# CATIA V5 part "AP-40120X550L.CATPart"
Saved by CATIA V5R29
Part number: AP-40120X550L
Bounding box of the stored display mesh (mm): x -275 to 275, y -60 to 60, z -20 to 20
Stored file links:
  C:\Users\Administrator\Desktop\프로젝트\Boxfold\AP-40120X550L.CATPart
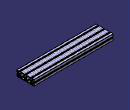
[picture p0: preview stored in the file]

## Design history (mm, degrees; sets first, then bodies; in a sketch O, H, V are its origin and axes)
Body1 (main body)
  Sketch1 on yz-plane, origin (0, 0, 0), H (0, 1, 0), V (0, 0, 1)
    point P1 (-60, -19)
    circle A1 centre (53.5, -13.5) radius 4
    circle A2 centre (53.5, 13.5) radius 4
    circle A3 centre (-53.5, -13.5) radius 4
    circle A4 centre (-53.5, 13.5) radius 4
    arc A5 centre (-38.0088, -3.1185) radius 0.3 from (-37.7966, -2.9064) to (-38.1702, -2.8656) ccw
    line L1 (-37.7966, -2.9064) -> (-37.1018, -3.6012)
    arc A6 centre (-36.8897, -3.3891) radius 0.3 from (-37.1018, -3.6012) to (-36.6868, -3.6101) ccw
    arc A7 centre (-40, 0) radius 4.9 from (-36.6868, -3.6101) to (-36.3857, -3.3086) ccw
    arc A8 centre (-36.607, -3.106) radius 0.3 from (-36.3857, -3.3086) to (-36.3949, -2.8939) ccw
    line L2 (-36.3949, -2.8939) -> (-37.0904, -2.1983)
    arc A9 centre (-36.8783, -1.9862) radius 0.3 from (-37.1314, -1.8252) to (-37.0904, -2.1983) ccw
    arc A10 centre (-40, 0) radius 3.4 from (-37.1314, -1.8252) to (-37.1323, 1.8265) ccw
    arc A11 centre (-36.8792, 1.9877) radius 0.3 from (-37.0914, 2.1998) to (-37.1323, 1.8265) ccw
    line L3 (-37.0914, 2.1998) -> (-36.396, 2.8952)
    arc A12 centre (-36.6081, 3.1073) radius 0.3 from (-36.396, 2.8952) to (-36.3869, 3.31) ccw
    arc A13 centre (-40, 0) radius 4.9 from (-36.3869, 3.31) to (-36.6881, 3.6113) ccw
    arc A14 centre (-36.8909, 3.3902) radius 0.3 from (-36.6881, 3.6113) to (-37.103, 3.6024) ccw
    line L4 (-37.103, 3.6024) -> (-37.7981, 2.9073)
    arc A15 centre (-38.0102, 3.1194) radius 0.3 from (-38.1716, 2.8665) to (-37.7981, 2.9073) ccw
    arc A16 centre (-40, 0) radius 3.4 from (-38.1716, 2.8665) to (-41.8252, 2.8686) ccw
    arc A17 centre (-41.9862, 3.1217) radius 0.3 from (-42.1983, 2.9096) to (-41.8252, 2.8686) ccw
    line L5 (-42.1983, 2.9096) -> (-42.8939, 3.6051)
    arc A18 centre (-43.106, 3.393) radius 0.3 from (-42.8939, 3.6051) to (-43.3086, 3.6143) ccw
    arc A19 centre (-40, 0) radius 4.9 from (-43.3086, 3.6143) to (-43.6101, 3.3132) ccw
    arc A20 centre (-43.3891, 3.1103) radius 0.3 from (-43.6101, 3.3132) to (-43.6012, 2.8982) ccw
    line L6 (-43.6012, 2.8982) -> (-42.9064, 2.2034)
    arc A21 centre (-43.1185, 1.9912) radius 0.3 from (-42.8656, 1.8298) to (-42.9064, 2.2034) ccw
    arc A22 centre (-40, 0) radius 3.4 from (-42.8656, 1.8298) to (-42.8665, -1.8284) ccw
    arc A23 centre (-43.1194, -1.9898) radius 0.3 from (-42.9073, -2.2019) to (-42.8665, -1.8284) ccw
    line L7 (-42.9073, -2.2019) -> (-43.6024, -2.897)
    arc A24 centre (-43.3902, -3.1091) radius 0.3 from (-43.6024, -2.897) to (-43.6113, -3.3119) ccw
    arc A25 centre (-40, 0) radius 4.9 from (-43.6113, -3.3119) to (-43.31, -3.6131) ccw
    arc A26 centre (-43.1073, -3.3919) radius 0.3 from (-43.31, -3.6131) to (-42.8952, -3.604) ccw
    line L8 (-42.8952, -3.604) -> (-42.1998, -2.9086)
    arc A27 centre (-41.9877, -3.1208) radius 0.3 from (-41.8265, -2.8677) to (-42.1998, -2.9086) ccw
    arc A28 centre (-40, 0) radius 3.4 from (-41.8265, -2.8677) to (-38.1702, -2.8656) ccw
    line L9 (39.6951, 6.0049) -> (40, 5.7)
    line L10 (40, 5.7) -> (40.3049, 6.0049)
    arc A29 centre (40, 15.5) radius 9.5 from (40.3049, 6.0049) to (47.0734, 9.1583) ccw
    arc A30 centre (46.85, 9.3585) radius 0.3 from (47.0734, 9.1583) to (47.15, 9.3585) ccw
    line L11 (47.15, 9.3585) -> (47.15, 15.7)
    arc A31 centre (46.85, 15.7) radius 0.3 from (47.15, 15.7) to (46.85, 16) ccw
    line L12 (46.85, 16) -> (44.65, 16)
    arc A32 centre (44.65, 16.5) radius 0.5 from (44.15, 16.5) to (44.65, 16) ccw
    line L13 (44.15, 16.5) -> (44.15, 19.5)
    arc A33 centre (44.65, 19.5) radius 0.5 from (44.65, 20) to (44.15, 19.5) ccw
    line L14 (44.65, 20) -> (59, 20)
    arc A34 centre (59, 19) radius 1 from (60, 19) to (59, 20) ccw
    line L15 (60, 19) -> (60, 4.65)
    arc A35 centre (59.5, 4.65) radius 0.5 from (59.5, 4.15) to (60, 4.65) ccw
    line L16 (59.5, 4.15) -> (56.5, 4.15)
    arc A36 centre (56.5, 4.65) radius 0.5 from (56, 4.65) to (56.5, 4.15) ccw
    line L17 (56, 4.65) -> (56, 6.85)
    arc A37 centre (55.7, 6.85) radius 0.3 from (56, 6.85) to (55.7, 7.15) ccw
    line L18 (55.7, 7.15) -> (49.3585, 7.15)
    arc A38 centre (49.3585, 6.85) radius 0.3 from (49.3585, 7.15) to (49.1583, 7.0734) ccw
    arc A39 centre (55.5, 0) radius 9.5 from (49.1583, 7.0734) to (46.0049, 0.3049) ccw
    line L19 (46.0049, 0.3049) -> (45.7, 0)
    line L20 (45.7, 0) -> (46.0049, -0.3049)
    arc A40 centre (55.5, 0) radius 9.5 from (46.0049, -0.3049) to (49.1583, -7.0734) ccw
    arc A41 centre (49.3585, -6.85) radius 0.3 from (49.1583, -7.0734) to (49.3585, -7.15) ccw
    line L21 (49.3585, -7.15) -> (55.7, -7.15)
    arc A42 centre (55.7, -6.85) radius 0.3 from (55.7, -7.15) to (56, -6.85) ccw
    line L22 (56, -6.85) -> (56, -4.65)
    arc A43 centre (56.5, -4.65) radius 0.5 from (56.5, -4.15) to (56, -4.65) ccw
    line L23 (56.5, -4.15) -> (59.5, -4.15)
    arc A44 centre (59.5, -4.65) radius 0.5 from (60, -4.65) to (59.5, -4.15) ccw
    line L24 (60, -4.65) -> (60, -19)
    arc A45 centre (59, -19) radius 1 from (59, -20) to (60, -19) ccw
    line L25 (59, -20) -> (44.65, -20)
    arc A46 centre (44.65, -19.5) radius 0.5 from (44.15, -19.5) to (44.65, -20) ccw
    line L26 (44.15, -19.5) -> (44.15, -16.5)
    arc A47 centre (44.65, -16.5) radius 0.5 from (44.65, -16) to (44.15, -16.5) ccw
    line L27 (44.65, -16) -> (46.85, -16)
    arc A48 centre (46.85, -15.7) radius 0.3 from (46.85, -16) to (47.15, -15.7) ccw
    line L28 (47.15, -15.7) -> (47.15, -9.3585)
    arc A49 centre (46.85, -9.3585) radius 0.3 from (47.15, -9.3585) to (47.0734, -9.1583) ccw
    arc A50 centre (40, -15.5) radius 9.5 from (47.0734, -9.1583) to (40.3049, -6.0049) ccw
    line L29 (40.3049, -6.0049) -> (40, -5.7)
    line L30 (40, -5.7) -> (39.6951, -6.0049)
    arc A51 centre (40, -15.5) radius 9.5 from (39.6951, -6.0049) to (32.9266, -9.1583) ccw
    arc A52 centre (33.15, -9.3585) radius 0.3 from (32.9266, -9.1583) to (32.85, -9.3585) ccw
    line L31 (32.85, -9.3585) -> (32.85, -15.7)
    arc A53 centre (33.15, -15.7) radius 0.3 from (32.85, -15.7) to (33.15, -16) ccw
    line L32 (33.15, -16) -> (35.35, -16)
    arc A54 centre (35.35, -16.5) radius 0.5 from (35.85, -16.5) to (35.35, -16) ccw
    line L33 (35.85, -16.5) -> (35.85, -19.5)
    arc A55 centre (35.35, -19.5) radius 0.5 from (35.35, -20) to (35.85, -19.5) ccw
    line L34 (35.35, -20) -> (4.65, -20)
    arc A56 centre (4.65, -19.5) radius 0.5 from (4.15, -19.5) to (4.65, -20) ccw
    line L35 (4.15, -19.5) -> (4.15, -16.5)
    arc A57 centre (4.65, -16.5) radius 0.5 from (4.65, -16) to (4.15, -16.5) ccw
    line L36 (4.65, -16) -> (6.85, -16)
    arc A58 centre (6.85, -15.7) radius 0.3 from (6.85, -16) to (7.15, -15.7) ccw
    line L37 (7.15, -15.7) -> (7.15, -9.3585)
    arc A59 centre (6.85, -9.3585) radius 0.3 from (7.15, -9.3585) to (7.0734, -9.1583) ccw
    arc A60 centre (0, -15.5) radius 9.5 from (7.0734, -9.1583) to (0.3049, -6.0049) ccw
    line L38 (0.3049, -6.0049) -> (0, -5.7)
    line L39 (0, -5.7) -> (-0.3049, -6.0049)
    arc A61 centre (0, -15.5) radius 9.5 from (-0.3049, -6.0049) to (-7.0734, -9.1583) ccw
    arc A62 centre (-6.85, -9.3585) radius 0.3 from (-7.0734, -9.1583) to (-7.15, -9.3585) ccw
    line L40 (-7.15, -9.3585) -> (-7.15, -15.7)
    arc A63 centre (-6.85, -15.7) radius 0.3 from (-7.15, -15.7) to (-6.85, -16) ccw
    line L41 (-6.85, -16) -> (-4.65, -16)
    arc A64 centre (-4.65, -16.5) radius 0.5 from (-4.15, -16.5) to (-4.65, -16) ccw
    line L42 (-4.15, -16.5) -> (-4.15, -19.5)
    arc A65 centre (-4.65, -19.5) radius 0.5 from (-4.65, -20) to (-4.15, -19.5) ccw
    line L43 (-4.65, -20) -> (-35.35, -20)
    arc A66 centre (-35.35, -19.5) radius 0.5 from (-35.85, -19.5) to (-35.35, -20) ccw
    line L44 (-35.85, -19.5) -> (-35.85, -16.5)
    arc A67 centre (-35.35, -16.5) radius 0.5 from (-35.35, -16) to (-35.85, -16.5) ccw
    line L45 (-35.35, -16) -> (-33.15, -16)
    arc A68 centre (-33.15, -15.7) radius 0.3 from (-33.15, -16) to (-32.85, -15.7) ccw
    line L46 (-32.85, -15.7) -> (-32.85, -9.3585)
    arc A69 centre (-33.15, -9.3585) radius 0.3 from (-32.85, -9.3585) to (-32.9266, -9.1583) ccw
    arc A70 centre (-40, -15.5) radius 9.5 from (-32.9266, -9.1583) to (-39.6951, -6.0049) ccw
    line L47 (-39.6951, -6.0049) -> (-40, -5.7)
    line L48 (-40, -5.7) -> (-40.3049, -6.0049)
    arc A71 centre (-40, -15.5) radius 9.5 from (-40.3049, -6.0049) to (-47.0734, -9.1583) ccw
    arc A72 centre (-46.85, -9.3585) radius 0.3 from (-47.0734, -9.1583) to (-47.15, -9.3585) ccw
    line L49 (-47.15, -9.3585) -> (-47.15, -15.7)
    arc A73 centre (-46.85, -15.7) radius 0.3 from (-47.15, -15.7) to (-46.85, -16) ccw
    line L50 (-46.85, -16) -> (-44.65, -16)
    arc A74 centre (-44.65, -16.5) radius 0.5 from (-44.15, -16.5) to (-44.65, -16) ccw
    line L51 (-44.15, -16.5) -> (-44.15, -19.5)
    arc A75 centre (-44.65, -19.5) radius 0.5 from (-44.65, -20) to (-44.15, -19.5) ccw
    line L52 (-44.65, -20) -> (-58, -20)
    line L53 (-58, -20) -> (-59, -20)
    arc A76 centre (-59, -19) radius 1 from (-60, -19) to (-59, -20) ccw
    line L54 (-60, -19) -> (-60, -4.65)
    arc A77 centre (-59.5, -4.65) radius 0.5 from (-59.5, -4.15) to (-60, -4.65) ccw
    line L55 (-59.5, -4.15) -> (-56.5, -4.15)
    arc A78 centre (-56.5, -4.65) radius 0.5 from (-56, -4.65) to (-56.5, -4.15) ccw
    line L56 (-56, -4.65) -> (-56, -6.85)
    arc A79 centre (-55.7, -6.85) radius 0.3 from (-56, -6.85) to (-55.7, -7.15) ccw
    line L57 (-55.7, -7.15) -> (-49.3585, -7.15)
    arc A80 centre (-49.3585, -6.85) radius 0.3 from (-49.3585, -7.15) to (-49.1583, -7.0734) ccw
    arc A81 centre (-55.5, 0) radius 9.5 from (-49.1583, -7.0734) to (-46.0049, -0.3049) ccw
    line L58 (-46.0049, -0.3049) -> (-45.7, 0)
    line L59 (-45.7, 0) -> (-46.0049, 0.3049)
    arc A82 centre (-55.5, 0) radius 9.5 from (-46.0049, 0.3049) to (-49.1583, 7.0734) ccw
    arc A83 centre (-49.3585, 6.85) radius 0.3 from (-49.1583, 7.0734) to (-49.3585, 7.15) ccw
    line L60 (-49.3585, 7.15) -> (-55.7, 7.15)
    arc A84 centre (-55.7, 6.85) radius 0.3 from (-55.7, 7.15) to (-56, 6.85) ccw
    line L61 (-56, 6.85) -> (-56, 4.65)
    arc A85 centre (-56.5, 4.65) radius 0.5 from (-56.5, 4.15) to (-56, 4.65) ccw
    line L62 (-56.5, 4.15) -> (-59.5, 4.15)
    arc A86 centre (-59.5, 4.65) radius 0.5 from (-60, 4.65) to (-59.5, 4.15) ccw
    line L63 (-60, 4.65) -> (-60, 19)
    arc A87 centre (-59, 19) radius 1 from (-59, 20) to (-60, 19) ccw
    line L64 (-59, 20) -> (-58, 20)
    line L65 (-58, 20) -> (-44.65, 20)
    arc A88 centre (-44.65, 19.5) radius 0.5 from (-44.15, 19.5) to (-44.65, 20) ccw
    line L66 (-44.15, 19.5) -> (-44.15, 16.5)
    arc A89 centre (-44.65, 16.5) radius 0.5 from (-44.65, 16) to (-44.15, 16.5) ccw
    line L67 (-44.65, 16) -> (-46.85, 16)
    arc A90 centre (-46.85, 15.7) radius 0.3 from (-46.85, 16) to (-47.15, 15.7) ccw
    line L68 (-47.15, 15.7) -> (-47.15, 9.3585)
    arc A91 centre (-46.85, 9.3585) radius 0.3 from (-47.15, 9.3585) to (-47.0734, 9.1583) ccw
    arc A92 centre (-40, 15.5) radius 9.5 from (-47.0734, 9.1583) to (-40.3049, 6.0049) ccw
    line L69 (-40.3049, 6.0049) -> (-40, 5.7)
    line L70 (-40, 5.7) -> (-39.6951, 6.0049)
    arc A93 centre (-40, 15.5) radius 9.5 from (-39.6951, 6.0049) to (-32.9266, 9.1583) ccw
    arc A94 centre (-33.15, 9.3585) radius 0.3 from (-32.9266, 9.1583) to (-32.85, 9.3585) ccw
    line L71 (-32.85, 9.3585) -> (-32.85, 15.7)
    arc A95 centre (-33.15, 15.7) radius 0.3 from (-32.85, 15.7) to (-33.15, 16) ccw
    line L72 (-33.15, 16) -> (-35.35, 16)
    arc A96 centre (-35.35, 16.5) radius 0.5 from (-35.85, 16.5) to (-35.35, 16) ccw
    line L73 (-35.85, 16.5) -> (-35.85, 19.5)
    arc A97 centre (-35.35, 19.5) radius 0.5 from (-35.35, 20) to (-35.85, 19.5) ccw
    line L74 (-35.35, 20) -> (-4.65, 20)
    arc A98 centre (-4.65, 19.5) radius 0.5 from (-4.15, 19.5) to (-4.65, 20) ccw
    line L75 (-4.15, 19.5) -> (-4.15, 16.5)
    arc A99 centre (-4.65, 16.5) radius 0.5 from (-4.65, 16) to (-4.15, 16.5) ccw
    line L76 (-4.65, 16) -> (-6.85, 16)
    arc A100 centre (-6.85, 15.7) radius 0.3 from (-6.85, 16) to (-7.15, 15.7) ccw
    line L77 (-7.15, 15.7) -> (-7.15, 9.3585)
    arc A101 centre (-6.85, 9.3585) radius 0.3 from (-7.15, 9.3585) to (-7.0734, 9.1583) ccw
    arc A102 centre (0, 15.5) radius 9.5 from (-7.0734, 9.1583) to (-0.3049, 6.0049) ccw
    line L78 (-0.3049, 6.0049) -> (0, 5.7)
    line L79 (0, 5.7) -> (0.3049, 6.0049)
    arc A103 centre (0, 15.5) radius 9.5 from (0.3049, 6.0049) to (7.0734, 9.1583) ccw
    arc A104 centre (6.85, 9.3585) radius 0.3 from (7.0734, 9.1583) to (7.15, 9.3585) ccw
    line L80 (7.15, 9.3585) -> (7.15, 15.7)
    arc A105 centre (6.85, 15.7) radius 0.3 from (7.15, 15.7) to (6.85, 16) ccw
    line L81 (6.85, 16) -> (4.65, 16)
    arc A106 centre (4.65, 16.5) radius 0.5 from (4.15, 16.5) to (4.65, 16) ccw
    line L82 (4.15, 16.5) -> (4.15, 19.5)
    arc A107 centre (4.65, 19.5) radius 0.5 from (4.65, 20) to (4.15, 19.5) ccw
    line L83 (4.65, 20) -> (35.35, 20)
    arc A108 centre (35.35, 19.5) radius 0.5 from (35.85, 19.5) to (35.35, 20) ccw
    line L84 (35.85, 19.5) -> (35.85, 16.5)
    arc A109 centre (35.35, 16.5) radius 0.5 from (35.35, 16) to (35.85, 16.5) ccw
    line L85 (35.35, 16) -> (33.15, 16)
    arc A110 centre (33.15, 15.7) radius 0.3 from (33.15, 16) to (32.85, 15.7) ccw
    line L86 (32.85, 15.7) -> (32.85, 9.3585)
    arc A111 centre (33.15, 9.3585) radius 0.3 from (32.85, 9.3585) to (32.9266, 9.1583) ccw
    arc A112 centre (40, 15.5) radius 9.5 from (32.9266, 9.1583) to (39.6951, 6.0049) ccw
    arc A113 centre (13.15, -14) radius 3 from (10.15, -14) to (13.15, -17) ccw
    line L87 (13.15, -17) -> (26.85, -17)
    arc A114 centre (26.85, -14) radius 3 from (26.85, -17) to (29.85, -14) ccw
    line L88 (29.85, -14) -> (29.85, -8.9422)
    arc A115 centre (20, -0.0053) radius 13.3 from (29.85, -8.9422) to (29.85, 8.9315) ccw
    line L89 (29.85, 8.9315) -> (29.85, 14)
    arc A116 centre (26.85, 14) radius 3 from (29.85, 14) to (26.85, 17) ccw
    line L90 (26.85, 17) -> (13.15, 17)
    arc A117 centre (13.15, 14) radius 3 from (13.15, 17) to (10.15, 14) ccw
    line L91 (10.15, 14) -> (10.15, 8.9315)
    arc A118 centre (20, -0.0053) radius 13.3 from (10.15, 8.9315) to (10.15, -8.9422) ccw
    line L92 (10.15, -8.9422) -> (10.15, -14)
    arc A119 centre (1.9912, -3.1185) radius 0.3 from (2.2034, -2.9064) to (1.8298, -2.8656) ccw
    line L93 (2.2034, -2.9064) -> (2.8982, -3.6012)
    arc A120 centre (3.1103, -3.3891) radius 0.3 from (2.8982, -3.6012) to (3.3132, -3.6101) ccw
    arc A121 centre (0, 0) radius 4.9 from (3.3132, -3.6101) to (3.6143, -3.3086) ccw
    arc A122 centre (3.393, -3.106) radius 0.3 from (3.6143, -3.3086) to (3.6051, -2.8939) ccw
    line L94 (3.6051, -2.8939) -> (2.9096, -2.1983)
    arc A123 centre (3.1217, -1.9862) radius 0.3 from (2.8686, -1.8252) to (2.9096, -2.1983) ccw
    arc A124 centre (0, 0) radius 3.4 from (2.8686, -1.8252) to (2.8677, 1.8265) ccw
    arc A125 centre (3.1208, 1.9877) radius 0.3 from (2.9086, 2.1998) to (2.8677, 1.8265) ccw
    line L95 (2.9086, 2.1998) -> (3.604, 2.8952)
    arc A126 centre (3.3919, 3.1073) radius 0.3 from (3.604, 2.8952) to (3.6131, 3.31) ccw
    arc A127 centre (0, 0) radius 4.9 from (3.6131, 3.31) to (3.3119, 3.6113) ccw
    arc A128 centre (3.1091, 3.3902) radius 0.3 from (3.3119, 3.6113) to (2.897, 3.6024) ccw
    line L96 (2.897, 3.6024) -> (2.2019, 2.9073)
    arc A129 centre (1.9898, 3.1194) radius 0.3 from (1.8284, 2.8665) to (2.2019, 2.9073) ccw
    arc A130 centre (0, 0) radius 3.4 from (1.8284, 2.8665) to (-1.8252, 2.8686) ccw
    arc A131 centre (-1.9862, 3.1217) radius 0.3 from (-2.1983, 2.9096) to (-1.8252, 2.8686) ccw
    line L97 (-2.1983, 2.9096) -> (-2.8939, 3.6051)
    arc A132 centre (-3.106, 3.393) radius 0.3 from (-2.8939, 3.6051) to (-3.3086, 3.6143) ccw
    arc A133 centre (0, 0) radius 4.9 from (-3.3086, 3.6143) to (-3.6101, 3.3132) ccw
    arc A134 centre (-3.3891, 3.1103) radius 0.3 from (-3.6101, 3.3132) to (-3.6012, 2.8982) ccw
    line L98 (-3.6012, 2.8982) -> (-2.9064, 2.2034)
    arc A135 centre (-3.1185, 1.9912) radius 0.3 from (-2.8656, 1.8298) to (-2.9064, 2.2034) ccw
    arc A136 centre (0, 0) radius 3.4 from (-2.8656, 1.8298) to (-2.8665, -1.8284) ccw
    arc A137 centre (-3.1194, -1.9898) radius 0.3 from (-2.9073, -2.2019) to (-2.8665, -1.8284) ccw
    line L99 (-2.9073, -2.2019) -> (-3.6024, -2.897)
    arc A138 centre (-3.3902, -3.1091) radius 0.3 from (-3.6024, -2.897) to (-3.6113, -3.3119) ccw
    arc A139 centre (0, 0) radius 4.9 from (-3.6113, -3.3119) to (-3.31, -3.6131) ccw
    arc A140 centre (-3.1073, -3.3919) radius 0.3 from (-3.31, -3.6131) to (-2.8952, -3.604) ccw
    line L100 (-2.8952, -3.604) -> (-2.1998, -2.9086)
    arc A141 centre (-1.9877, -3.1208) radius 0.3 from (-1.8265, -2.8677) to (-2.1998, -2.9086) ccw
    arc A142 centre (0, 0) radius 3.4 from (-1.8265, -2.8677) to (1.8298, -2.8656) ccw
    arc A143 centre (41.9912, -3.1185) radius 0.3 from (42.2034, -2.9064) to (41.8298, -2.8656) ccw
    line L101 (42.2034, -2.9064) -> (42.8982, -3.6012)
    arc A144 centre (43.1103, -3.3891) radius 0.3 from (42.8982, -3.6012) to (43.3132, -3.6101) ccw
    arc A145 centre (40, 0) radius 4.9 from (43.3132, -3.6101) to (43.6143, -3.3086) ccw
    arc A146 centre (43.393, -3.106) radius 0.3 from (43.6143, -3.3086) to (43.6051, -2.8939) ccw
    line L102 (43.6051, -2.8939) -> (42.9096, -2.1983)
    arc A147 centre (43.1217, -1.9862) radius 0.3 from (42.8686, -1.8252) to (42.9096, -2.1983) ccw
    arc A148 centre (40, 0) radius 3.4 from (42.8686, -1.8252) to (42.8677, 1.8265) ccw
    arc A149 centre (43.1208, 1.9877) radius 0.3 from (42.9086, 2.1998) to (42.8677, 1.8265) ccw
    line L103 (42.9086, 2.1998) -> (43.604, 2.8952)
    arc A150 centre (43.3919, 3.1073) radius 0.3 from (43.604, 2.8952) to (43.6131, 3.31) ccw
    arc A151 centre (40, 0) radius 4.9 from (43.6131, 3.31) to (43.3119, 3.6113) ccw
    arc A152 centre (43.1091, 3.3902) radius 0.3 from (43.3119, 3.6113) to (42.897, 3.6024) ccw
    line L104 (42.897, 3.6024) -> (42.2019, 2.9073)
    arc A153 centre (41.9898, 3.1194) radius 0.3 from (41.8284, 2.8665) to (42.2019, 2.9073) ccw
    arc A154 centre (40, 0) radius 3.4 from (41.8284, 2.8665) to (38.1748, 2.8686) ccw
    arc A155 centre (38.0138, 3.1217) radius 0.3 from (37.8017, 2.9096) to (38.1748, 2.8686) ccw
    line L105 (37.8017, 2.9096) -> (37.1061, 3.6051)
    arc A156 centre (36.894, 3.393) radius 0.3 from (37.1061, 3.6051) to (36.6914, 3.6143) ccw
    arc A157 centre (40, 0) radius 4.9 from (36.6914, 3.6143) to (36.3899, 3.3132) ccw
    arc A158 centre (36.6109, 3.1103) radius 0.3 from (36.3899, 3.3132) to (36.3988, 2.8982) ccw
    line L106 (36.3988, 2.8982) -> (37.0936, 2.2034)
    arc A159 centre (36.8815, 1.9912) radius 0.3 from (37.1344, 1.8298) to (37.0936, 2.2034) ccw
    arc A160 centre (40, 0) radius 3.4 from (37.1344, 1.8298) to (37.1335, -1.8284) ccw
    arc A161 centre (36.8806, -1.9898) radius 0.3 from (37.0927, -2.2019) to (37.1335, -1.8284) ccw
    line L107 (37.0927, -2.2019) -> (36.3976, -2.897)
    arc A162 centre (36.6098, -3.1091) radius 0.3 from (36.3976, -2.897) to (36.3887, -3.3119) ccw
    arc A163 centre (40, 0) radius 4.9 from (36.3887, -3.3119) to (36.69, -3.6131) ccw
    arc A164 centre (36.8927, -3.3919) radius 0.3 from (36.69, -3.6131) to (37.1048, -3.604) ccw
    line L108 (37.1048, -3.604) -> (37.8002, -2.9086)
    arc A165 centre (38.0123, -3.1208) radius 0.3 from (38.1735, -2.8677) to (37.8002, -2.9086) ccw
    arc A166 centre (40, 0) radius 3.4 from (38.1735, -2.8677) to (41.8298, -2.8656) ccw
    line L109 (-13.15, 17) -> (-26.85, 17)
    arc A167 centre (-26.85, 14) radius 3 from (-26.85, 17) to (-29.85, 14) ccw
    line L110 (-29.85, 14) -> (-29.85, 8.9315)
    arc A168 centre (-20, -0.0053) radius 13.3 from (-29.85, 8.9315) to (-29.85, -8.9422) ccw
    line L111 (-29.85, -8.9422) -> (-29.85, -14)
    arc A169 centre (-26.85, -14) radius 3 from (-29.85, -14) to (-26.85, -17) ccw
    line L112 (-26.85, -17) -> (-13.15, -17)
    arc A170 centre (-13.15, -14) radius 3 from (-13.15, -17) to (-10.15, -14) ccw
    line L113 (-10.15, -14) -> (-10.15, -8.9422)
    arc A171 centre (-20, -0.0053) radius 13.3 from (-10.15, -8.9422) to (-10.15, 8.9315) ccw
    line L114 (-10.15, 8.9315) -> (-10.15, 14)
    arc A172 centre (-13.15, 14) radius 3 from (-10.15, 14) to (-13.15, 17) ccw
    point P2 (-37.7966, -2.9064)
    point P3 (-38.1702, -2.8656)
    point P4 (-37.7966, -2.9064)
    point P5 (-37.1018, -3.6012)
    point P6 (-37.1018, -3.6012)
    point P7 (-36.6868, -3.6101)
    point P8 (-36.6868, -3.6101)
    point P9 (-36.3857, -3.3086)
    point P10 (-36.3857, -3.3086)
    point P11 (-36.3949, -2.8939)
    point P12 (-36.3949, -2.8939)
    point P13 (-37.0904, -2.1983)
    point P14 (-37.1314, -1.8252)
    point P15 (-37.0904, -2.1983)
    point P16 (-37.1314, -1.8252)
    point P17 (-37.1323, 1.8265)
    point P18 (-37.0914, 2.1998)
    point P19 (-37.1323, 1.8265)
    point P20 (-37.0914, 2.1998)
    point P21 (-36.396, 2.8952)
    point P22 (-36.396, 2.8952)
    point P23 (-36.3869, 3.31)
    point P24 (-36.3869, 3.31)
    point P25 (-36.6881, 3.6113)
    point P26 (-36.6881, 3.6113)
    point P27 (-37.103, 3.6024)
    point P28 (-37.103, 3.6024)
    point P29 (-37.7981, 2.9073)
    point P30 (-38.1716, 2.8665)
    point P31 (-37.7981, 2.9073)
    point P32 (-38.1716, 2.8665)
    point P33 (-41.8252, 2.8686)
    point P34 (-42.1983, 2.9096)
    point P35 (-41.8252, 2.8686)
    point P36 (-42.1983, 2.9096)
    point P37 (-42.8939, 3.6051)
    point P38 (-42.8939, 3.6051)
    point P39 (-43.3086, 3.6143)
    point P40 (-43.3086, 3.6143)
    point P41 (-43.6101, 3.3132)
    point P42 (-43.6101, 3.3132)
    point P43 (-43.6012, 2.8982)
    point P44 (-43.6012, 2.8982)
    point P45 (-42.9064, 2.2034)
    point P46 (-42.8656, 1.8298)
    point P47 (-42.9064, 2.2034)
    point P48 (-42.8656, 1.8298)
    point P49 (-42.8665, -1.8284)
    point P50 (-42.9073, -2.2019)
    point P51 (-42.8665, -1.8284)
    point P52 (-42.9073, -2.2019)
    point P53 (-43.6024, -2.897)
    point P54 (-43.6024, -2.897)
    point P55 (-43.6113, -3.3119)
    point P56 (-43.6113, -3.3119)
    point P57 (-43.31, -3.6131)
    point P58 (-43.31, -3.6131)
    point P59 (-42.8952, -3.604)
    point P60 (-42.8952, -3.604)
    point P61 (-42.1998, -2.9086)
    point P62 (-41.8265, -2.8677)
    point P63 (-42.1998, -2.9086)
    point P64 (-41.8265, -2.8677)
    point P65 (-38.1702, -2.8656)
    point P66 (39.6951, 6.0049)
    point P67 (40, 5.7)
    point P68 (40, 5.7)
    point P69 (40.3049, 6.0049)
    point P70 (40.3049, 6.0049)
    point P71 (47.0734, 9.1583)
    point P72 (47.0734, 9.1583)
    point P73 (47.15, 9.3585)
    point P74 (47.15, 9.3585)
    point P75 (47.15, 15.7)
    point P76 (47.15, 15.7)
    point P77 (46.85, 16)
    point P78 (46.85, 16)
    point P79 (44.65, 16)
    point P80 (44.15, 16.5)
    point P81 (44.65, 16)
    point P82 (44.15, 16.5)
    point P83 (44.15, 19.5)
    point P84 (44.65, 20)
    point P85 (44.15, 19.5)
    point P86 (44.65, 20)
    point P87 (59, 20)
    point P88 (60, 19)
    point P89 (59, 20)
    point P90 (60, 19)
    point P91 (60, 4.65)
    point P92 (59.5, 4.15)
    point P93 (60, 4.65)
    point P94 (59.5, 4.15)
    point P95 (56.5, 4.15)
    point P96 (56, 4.65)
    point P97 (56.5, 4.15)
    point P98 (56, 4.65)
    point P99 (56, 6.85)
    point P100 (56, 6.85)
    point P101 (55.7, 7.15)
    point P102 (55.7, 7.15)
    point P103 (49.3585, 7.15)
    point P104 (49.3585, 7.15)
    point P105 (49.1583, 7.0734)
    point P106 (49.1583, 7.0734)
    point P107 (46.0049, 0.3049)
    point P108 (46.0049, 0.3049)
    point P109 (45.7, 0)
    point P110 (45.7, 0)
    point P111 (46.0049, -0.3049)
    point P112 (46.0049, -0.3049)
    point P113 (49.1583, -7.0734)
    point P114 (49.1583, -7.0734)
    point P115 (49.3585, -7.15)
    point P116 (49.3585, -7.15)
    point P117 (55.7, -7.15)
    point P118 (55.7, -7.15)
    point P119 (56, -6.85)
    point P120 (56, -6.85)
    point P121 (56, -4.65)
    point P122 (56.5, -4.15)
    point P123 (56, -4.65)
    point P124 (56.5, -4.15)
    point P125 (59.5, -4.15)
    point P126 (60, -4.65)
    point P127 (59.5, -4.15)
    point P128 (60, -4.65)
    point P129 (60, -19)
    point P130 (59, -20)
    point P131 (60, -19)
    point P132 (59, -20)
    point P133 (44.65, -20)
    point P134 (44.15, -19.5)
    point P135 (44.65, -20)
    point P136 (44.15, -19.5)
    point P137 (44.15, -16.5)
    point P138 (44.65, -16)
    point P139 (44.15, -16.5)
    point P140 (44.65, -16)
    point P141 (46.85, -16)
    point P142 (46.85, -16)
    point P143 (47.15, -15.7)
    point P144 (47.15, -15.7)
    point P145 (47.15, -9.3585)
    point P146 (47.15, -9.3585)
    point P147 (47.0734, -9.1583)
    point P148 (47.0734, -9.1583)
    point P149 (40.3049, -6.0049)
    point P150 (40.3049, -6.0049)
    point P151 (40, -5.7)
    point P152 (40, -5.7)
    point P153 (39.6951, -6.0049)
    point P154 (39.6951, -6.0049)
    point P155 (32.9266, -9.1583)
    point P156 (32.9266, -9.1583)
    point P157 (32.85, -9.3585)
    point P158 (32.85, -9.3585)
    point P159 (32.85, -15.7)
    point P160 (32.85, -15.7)
    point P161 (33.15, -16)
    point P162 (33.15, -16)
    point P163 (35.35, -16)
    point P164 (35.85, -16.5)
    point P165 (35.35, -16)
    point P166 (35.85, -16.5)
    point P167 (35.85, -19.5)
    point P168 (35.35, -20)
    point P169 (35.85, -19.5)
    point P170 (35.35, -20)
    point P171 (4.65, -20)
    point P172 (4.15, -19.5)
    point P173 (4.65, -20)
    point P174 (4.15, -19.5)
    point P175 (4.15, -16.5)
    point P176 (4.65, -16)
    point P177 (4.15, -16.5)
    point P178 (4.65, -16)
    point P179 (6.85, -16)
    point P180 (6.85, -16)
    point P181 (7.15, -15.7)
    point P182 (7.15, -15.7)
    point P183 (7.15, -9.3585)
    point P184 (7.15, -9.3585)
    point P185 (7.0734, -9.1583)
    point P186 (7.0734, -9.1583)
    point P187 (0.3049, -6.0049)
    point P188 (0.3049, -6.0049)
    point P189 (0, -5.7)
    point P190 (0, -5.7)
    point P191 (-0.3049, -6.0049)
    point P192 (-0.3049, -6.0049)
    point P193 (-7.0734, -9.1583)
    point P194 (-7.0734, -9.1583)
    point P195 (-7.15, -9.3585)
    point P196 (-7.15, -9.3585)
    point P197 (-7.15, -15.7)
    point P198 (-7.15, -15.7)
    point P199 (-6.85, -16)
    point P200 (-6.85, -16)
    point P201 (-4.65, -16)
    point P202 (-4.15, -16.5)
    point P203 (-4.65, -16)
    point P204 (-4.15, -16.5)
    point P205 (-4.15, -19.5)
    point P206 (-4.65, -20)
    point P207 (-4.15, -19.5)
    point P208 (-4.65, -20)
    point P209 (-35.35, -20)
    point P210 (-35.85, -19.5)
    point P211 (-35.35, -20)
    point P212 (-35.85, -19.5)
    point P213 (-35.85, -16.5)
    point P214 (-35.35, -16)
    point P215 (-35.85, -16.5)
    point P216 (-35.35, -16)
    point P217 (-33.15, -16)
    point P218 (-33.15, -16)
    point P219 (-32.85, -15.7)
    point P220 (-32.85, -15.7)
    point P221 (-32.85, -9.3585)
    point P222 (-32.85, -9.3585)
    point P223 (-32.9266, -9.1583)
    point P224 (-32.9266, -9.1583)
    point P225 (-39.6951, -6.0049)
    point P226 (-39.6951, -6.0049)
    point P227 (-40, -5.7)
    point P228 (-40, -5.7)
    point P229 (-40.3049, -6.0049)
    point P230 (-40.3049, -6.0049)
    point P231 (-47.0734, -9.1583)
    point P232 (-47.0734, -9.1583)
    point P233 (-47.15, -9.3585)
    point P234 (-47.15, -9.3585)
    point P235 (-47.15, -15.7)
    point P236 (-47.15, -15.7)
    point P237 (-46.85, -16)
    point P238 (-46.85, -16)
    point P239 (-44.65, -16)
    point P240 (-44.15, -16.5)
    point P241 (-44.65, -16)
    point P242 (-44.15, -16.5)
    point P243 (-44.15, -19.5)
    point P244 (-44.65, -20)
    point P245 (-44.15, -19.5)
    point P246 (-44.65, -20)
    point P247 (-58, -20)
    point P248 (-58, -20)
    point P249 (-59, -20)
    point P250 (-60, -19)
    point P251 (-59, -20)
    point P252 (-60, -19)
    point P253 (-60, -4.65)
    point P254 (-59.5, -4.15)
    point P255 (-60, -4.65)
    point P256 (-59.5, -4.15)
    point P257 (-56.5, -4.15)
    point P258 (-56, -4.65)
    point P259 (-56.5, -4.15)
    point P260 (-56, -4.65)
    point P261 (-56, -6.85)
    point P262 (-56, -6.85)
    point P263 (-55.7, -7.15)
    point P264 (-55.7, -7.15)
    point P265 (-49.3585, -7.15)
    point P266 (-49.3585, -7.15)
    point P267 (-49.1583, -7.0734)
    point P268 (-49.1583, -7.0734)
    point P269 (-46.0049, -0.3049)
    point P270 (-46.0049, -0.3049)
    point P271 (-45.7, 0)
    point P272 (-45.7, 0)
    point P273 (-46.0049, 0.3049)
    point P274 (-46.0049, 0.3049)
    point P275 (-49.1583, 7.0734)
    point P276 (-49.1583, 7.0734)
    point P277 (-49.3585, 7.15)
    point P278 (-49.3585, 7.15)
    point P279 (-55.7, 7.15)
    point P280 (-55.7, 7.15)
    point P281 (-56, 6.85)
    point P282 (-56, 6.85)
    point P283 (-56, 4.65)
    point P284 (-56.5, 4.15)
    point P285 (-56, 4.65)
    point P286 (-56.5, 4.15)
    point P287 (-59.5, 4.15)
    point P288 (-60, 4.65)
    point P289 (-59.5, 4.15)
    point P290 (-60, 4.65)
    point P291 (-60, 19)
    point P292 (-59, 20)
    point P293 (-60, 19)
    point P294 (-59, 20)
    point P295 (-58, 20)
    point P296 (-58, 20)
    point P297 (-44.65, 20)
    point P298 (-44.15, 19.5)
    point P299 (-44.65, 20)
    point P300 (-44.15, 19.5)
    point P301 (-44.15, 16.5)
    point P302 (-44.65, 16)
    point P303 (-44.15, 16.5)
    point P304 (-44.65, 16)
    point P305 (-46.85, 16)
    point P306 (-46.85, 16)
    point P307 (-47.15, 15.7)
    point P308 (-47.15, 15.7)
    point P309 (-47.15, 9.3585)
    point P310 (-47.15, 9.3585)
    point P311 (-47.0734, 9.1583)
    point P312 (-47.0734, 9.1583)
    point P313 (-40.3049, 6.0049)
    point P314 (-40.3049, 6.0049)
    point P315 (-40, 5.7)
    point P316 (-40, 5.7)
    point P317 (-39.6951, 6.0049)
    point P318 (-39.6951, 6.0049)
    point P319 (-32.9266, 9.1583)
    point P320 (-32.9266, 9.1583)
    point P321 (-32.85, 9.3585)
    point P322 (-32.85, 9.3585)
    point P323 (-32.85, 15.7)
    point P324 (-32.85, 15.7)
    point P325 (-33.15, 16)
    point P326 (-33.15, 16)
    point P327 (-35.35, 16)
    point P328 (-35.85, 16.5)
    point P329 (-35.35, 16)
    point P330 (-35.85, 16.5)
    point P331 (-35.85, 19.5)
    point P332 (-35.35, 20)
    point P333 (-35.85, 19.5)
    point P334 (-35.35, 20)
    point P335 (-4.65, 20)
    point P336 (-4.15, 19.5)
    point P337 (-4.65, 20)
    point P338 (-4.15, 19.5)
    point P339 (-4.15, 16.5)
    point P340 (-4.65, 16)
    point P341 (-4.15, 16.5)
    point P342 (-4.65, 16)
    point P343 (-6.85, 16)
    point P344 (-6.85, 16)
    point P345 (-7.15, 15.7)
    point P346 (-7.15, 15.7)
    point P347 (-7.15, 9.3585)
    point P348 (-7.15, 9.3585)
    point P349 (-7.0734, 9.1583)
    point P350 (-7.0734, 9.1583)
    point P351 (-0.3049, 6.0049)
    point P352 (-0.3049, 6.0049)
    point P353 (0, 5.7)
    point P354 (0, 5.7)
    point P355 (0.3049, 6.0049)
    point P356 (0.3049, 6.0049)
    point P357 (7.0734, 9.1583)
    point P358 (7.0734, 9.1583)
    point P359 (7.15, 9.3585)
    point P360 (7.15, 9.3585)
    point P361 (7.15, 15.7)
    point P362 (7.15, 15.7)
    point P363 (6.85, 16)
    point P364 (6.85, 16)
    point P365 (4.65, 16)
    point P366 (4.15, 16.5)
    point P367 (4.65, 16)
    point P368 (4.15, 16.5)
    point P369 (4.15, 19.5)
    point P370 (4.65, 20)
    point P371 (4.15, 19.5)
    point P372 (4.65, 20)
    point P373 (35.35, 20)
    point P374 (35.85, 19.5)
    point P375 (35.35, 20)
    point P376 (35.85, 19.5)
    point P377 (35.85, 16.5)
    point P378 (35.35, 16)
    point P379 (35.85, 16.5)
    point P380 (35.35, 16)
    point P381 (33.15, 16)
    point P382 (33.15, 16)
    point P383 (32.85, 15.7)
    point P384 (32.85, 15.7)
    point P385 (32.85, 9.3585)
    point P386 (32.85, 9.3585)
    point P387 (32.9266, 9.1583)
    point P388 (32.9266, 9.1583)
    point P389 (39.6951, 6.0049)
    point P390 (10.15, -14)
    point P391 (13.15, -17)
    point P392 (13.15, -17)
    point P393 (26.85, -17)
    point P394 (26.85, -17)
    point P395 (29.85, -14)
    point P396 (29.85, -14)
    point P397 (29.85, -8.9422)
    point P398 (29.85, -8.9422)
    point P399 (29.85, 8.9315)
    point P400 (29.85, 8.9315)
    point P401 (29.85, 14)
    point P402 (29.85, 14)
    point P403 (26.85, 17)
    point P404 (26.85, 17)
    point P405 (13.15, 17)
    point P406 (13.15, 17)
    point P407 (10.15, 14)
    point P408 (10.15, 14)
    point P409 (10.15, 8.9315)
    point P410 (10.15, 8.9315)
    point P411 (10.15, -8.9422)
    point P412 (10.15, -8.9422)
    point P413 (10.15, -14)
    point P414 (2.2034, -2.9064)
    point P415 (1.8298, -2.8656)
    point P416 (2.2034, -2.9064)
    point P417 (2.8982, -3.6012)
    point P418 (2.8982, -3.6012)
    point P419 (3.3132, -3.6101)
    point P420 (3.3132, -3.6101)
    point P421 (3.6143, -3.3086)
    point P422 (3.6143, -3.3086)
    point P423 (3.6051, -2.8939)
    point P424 (3.6051, -2.8939)
    point P425 (2.9096, -2.1983)
    point P426 (2.8686, -1.8252)
    point P427 (2.9096, -2.1983)
    point P428 (2.8686, -1.8252)
    point P429 (2.8677, 1.8265)
    point P430 (2.9086, 2.1998)
    point P431 (2.8677, 1.8265)
    point P432 (2.9086, 2.1998)
    point P433 (3.604, 2.8952)
    point P434 (3.604, 2.8952)
    point P435 (3.6131, 3.31)
    point P436 (3.6131, 3.31)
    point P437 (3.3119, 3.6113)
    point P438 (3.3119, 3.6113)
    point P439 (2.897, 3.6024)
    point P440 (2.897, 3.6024)
    point P441 (2.2019, 2.9073)
    point P442 (1.8284, 2.8665)
    point P443 (2.2019, 2.9073)
    point P444 (1.8284, 2.8665)
    point P445 (-1.8252, 2.8686)
    point P446 (-2.1983, 2.9096)
    point P447 (-1.8252, 2.8686)
    point P448 (-2.1983, 2.9096)
    point P449 (-2.8939, 3.6051)
    point P450 (-2.8939, 3.6051)
    point P451 (-3.3086, 3.6143)
    point P452 (-3.3086, 3.6143)
    point P453 (-3.6101, 3.3132)
    point P454 (-3.6101, 3.3132)
    point P455 (-3.6012, 2.8982)
    point P456 (-3.6012, 2.8982)
    point P457 (-2.9064, 2.2034)
    point P458 (-2.8656, 1.8298)
    point P459 (-2.9064, 2.2034)
    point P460 (-2.8656, 1.8298)
    point P461 (-2.8665, -1.8284)
    point P462 (-2.9073, -2.2019)
    point P463 (-2.8665, -1.8284)
    point P464 (-2.9073, -2.2019)
    point P465 (-3.6024, -2.897)
    point P466 (-3.6024, -2.897)
    point P467 (-3.6113, -3.3119)
    point P468 (-3.6113, -3.3119)
    point P469 (-3.31, -3.6131)
    point P470 (-3.31, -3.6131)
    point P471 (-2.8952, -3.604)
    point P472 (-2.8952, -3.604)
    point P473 (-2.1998, -2.9086)
    point P474 (-1.8265, -2.8677)
    point P475 (-2.1998, -2.9086)
    point P476 (-1.8265, -2.8677)
    point P477 (1.8298, -2.8656)
    point P478 (42.2034, -2.9064)
    point P479 (41.8298, -2.8656)
    point P480 (42.2034, -2.9064)
    point P481 (42.8982, -3.6012)
    point P482 (42.8982, -3.6012)
    point P483 (43.3132, -3.6101)
    point P484 (43.3132, -3.6101)
    point P485 (43.6143, -3.3086)
    point P486 (43.6143, -3.3086)
    point P487 (43.6051, -2.8939)
    point P488 (43.6051, -2.8939)
    point P489 (42.9096, -2.1983)
    point P490 (42.8686, -1.8252)
    point P491 (42.9096, -2.1983)
    point P492 (42.8686, -1.8252)
    point P493 (42.8677, 1.8265)
    point P494 (42.9086, 2.1998)
    point P495 (42.8677, 1.8265)
    point P496 (42.9086, 2.1998)
    point P497 (43.604, 2.8952)
    point P498 (43.604, 2.8952)
    point P499 (43.6131, 3.31)
    point P500 (43.6131, 3.31)
    point P501 (43.3119, 3.6113)
    point P502 (43.3119, 3.6113)
    point P503 (42.897, 3.6024)
    point P504 (42.897, 3.6024)
    point P505 (42.2019, 2.9073)
    point P506 (41.8284, 2.8665)
    point P507 (42.2019, 2.9073)
    point P508 (41.8284, 2.8665)
    point P509 (38.1748, 2.8686)
    point P510 (37.8017, 2.9096)
    point P511 (38.1748, 2.8686)
    point P512 (37.8017, 2.9096)
    point P513 (37.1061, 3.6051)
    point P514 (37.1061, 3.6051)
    point P515 (36.6914, 3.6143)
    point P516 (36.6914, 3.6143)
    point P517 (36.3899, 3.3132)
    point P518 (36.3899, 3.3132)
    point P519 (36.3988, 2.8982)
    point P520 (36.3988, 2.8982)
    point P521 (37.0936, 2.2034)
    point P522 (37.1344, 1.8298)
    point P523 (37.0936, 2.2034)
    point P524 (37.1344, 1.8298)
    point P525 (37.1335, -1.8284)
    point P526 (37.0927, -2.2019)
    point P527 (37.1335, -1.8284)
    point P528 (37.0927, -2.2019)
    point P529 (36.3976, -2.897)
    point P530 (36.3976, -2.897)
    point P531 (36.3887, -3.3119)
    point P532 (36.3887, -3.3119)
    point P533 (36.69, -3.6131)
    point P534 (36.69, -3.6131)
    point P535 (37.1048, -3.604)
    point P536 (37.1048, -3.604)
    point P537 (37.8002, -2.9086)
    point P538 (38.1735, -2.8677)
    point P539 (37.8002, -2.9086)
    point P540 (38.1735, -2.8677)
    point P541 (41.8298, -2.8656)
    point P542 (-13.15, 17)
    point P543 (-26.85, 17)
    point P544 (-26.85, 17)
    point P545 (-29.85, 14)
    point P546 (-29.85, 14)
    point P547 (-29.85, 8.9315)
    point P548 (-29.85, 8.9315)
    point P549 (-29.85, -8.9422)
    point P550 (-29.85, -8.9422)
    point P551 (-29.85, -14)
    point P552 (-29.85, -14)
    point P553 (-26.85, -17)
    point P554 (-26.85, -17)
    point P555 (-13.15, -17)
    point P556 (-13.15, -17)
    point P557 (-10.15, -14)
    point P558 (-10.15, -14)
    point P559 (-10.15, -8.9422)
    point P560 (-10.15, -8.9422)
    point P561 (-10.15, 8.9315)
    point P562 (-10.15, 8.9315)
    point P563 (-10.15, 14)
    point P564 (-10.15, 14)
    point P565 (-13.15, 17)
    reference intersected line E1 through (0, 0) direction (0, 1) from zx-plane
    distance H L83 = 20
    distance L15 E1 = 60
    coincidence: P2 P4, P3 P65, P5 P6, P7 P8, P9 P10, P11 P12, P13 P15, P14 P16, P17 P19, P18 P20, P21 P22, P23 P24, P25 P26, P27 P28, P29 P31, P30 P32, P33 P35, P34 P36, P37 P38, P39 P40, P41 P42, P43 P44, P45 P47, P46 P48, P49 P51, P50 P52, P53 P54, P55 P56, P57 P58, P59 P60, P61 P63, P62 P64, P66 P389, P67 P68, P69 P70, P71 P72, P73 P74, P75 P76, P77 P78, P79 P81, P80 P82, P83 P85, P84 P86, P88 P90, P89 P87, P91 P93, P92 P94, P95 P97, P96 P98, P99 P100, P101 P102, P103 P104, P105 P106, P107 P108, P109 P110, P111 P112, P113 P114, P115 P116, P117 P118, P119 P120, P121 P123, P122 P124, P125 P127, P126 P128, P132 P130, P133 P135, P134 P136, P137 P139, P138 P140, P141 P142, P143 P144, P145 P146, P147 P148, P149 P150, P151 P152, P153 P154, P155 P156, P157 P158, P159 P160, P161 P162, P163 P165, P164 P166, P167 P169, P168 P170, P171 P173, P172 P174, P175 P177, P176 P178, P179 P180, P181 P182, P183 P184, P185 P186, P187 P188, P189 P190, P191 P192, P193 P194, P195 P196, P197 P198, P199 P200, P201 P203, P202 P204, P205 P207, P206 P208, P209 P211, P210 P212, P213 P215, P214 P216, P217 P218, P219 P220, P221 P222, P223 P224, P225 P226, P227 P228, P229 P230, P231 P232, P233 P234, P235 P236, P237 P238, P239 P241, P240 P242, P243 P245, P244 P246, P247 P248, P249 P251, P250 P252, P253 P255, P254 P256, P257 P259, P258 P260, P261 P262, P263 P264, P265 P266, P267 P268, P269 P270, P271 P272, P273 P274, P275 P276, P277 P278, P279 P280, P281 P282, P283 P285, P284 P286, P287 P289, P288 P290, P291 P293, P292 P294, P295 P296, P297 P299, P298 P300, P301 P303, P302 P304, P305 P306, P307 P308, P309 P310, P311 P312, P313 P314, P315 P316, P317 P318, P319 P320, P321 P322, P323 P324, P325 P326, P327 P329, P328 P330, P331 P333, P332 P334, P335 P337, P336 P338, P339 P341, P340 P342, P343 P344, P345 P346, P347 P348, P349 P350, P351 P352, P353 P354, P355 P356, P357 P358, P359 P360, P361 P362, P363 P364, P365 P367, P366 P368, P369 P371, P370 P372, P373 P375, P374 P376, P377 P379, P378 P380, P381 P382, P383 P384, P385 P386, P387 P388, P390 P413, P391 P392, P393 P394, P395 P396, P397 P398, P399 P400, P401 P402, P403 P404, P405 P406, P407 P408, P409 P410, P411 P412, P414 P416, P415 P477, P417 P418, P419 P420, P421 P422, P423 P424, P425 P427, P426 P428, P429 P431, P430 P432, P433 P434, P435 P436, P437 P438, P439 P440, P441 P443, P442 P444, P445 P447, P446 P448, P449 P450, P451 P452, P453 P454, P455 P456, P457 P459, P458 P460, P461 P463, P462 P464, P465 P466, P467 P468, P469 P470, P471 P472, P473 P475, P474 P476, P478 P480, P479 P541, P481 P482, P483 P484, P485 P486, P487 P488, P489 P491, P490 P492, P493 P495, P494 P496, P497 P498, P499 P500, P501 P502, P503 P504, P505 P507, P506 P508, P509 P511, P510 P512, P513 P514, P515 P516, P517 P518, P519 P520, P521 P523, P522 P524, P525 P527, P526 P528, P529 P530, P531 P532, P533 P534, P535 P536, P537 P539, P538 P540, P542 P565, P543 P544, P545 P546, P547 P548, P549 P550, P551 P552, P553 P554, P555 P556, P557 P558, P559 P560, P561 P562, P563 P564, P131 P129
  Pad1: profile Sketch1, direction (1, 0, 0), length 275, mirrored extent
